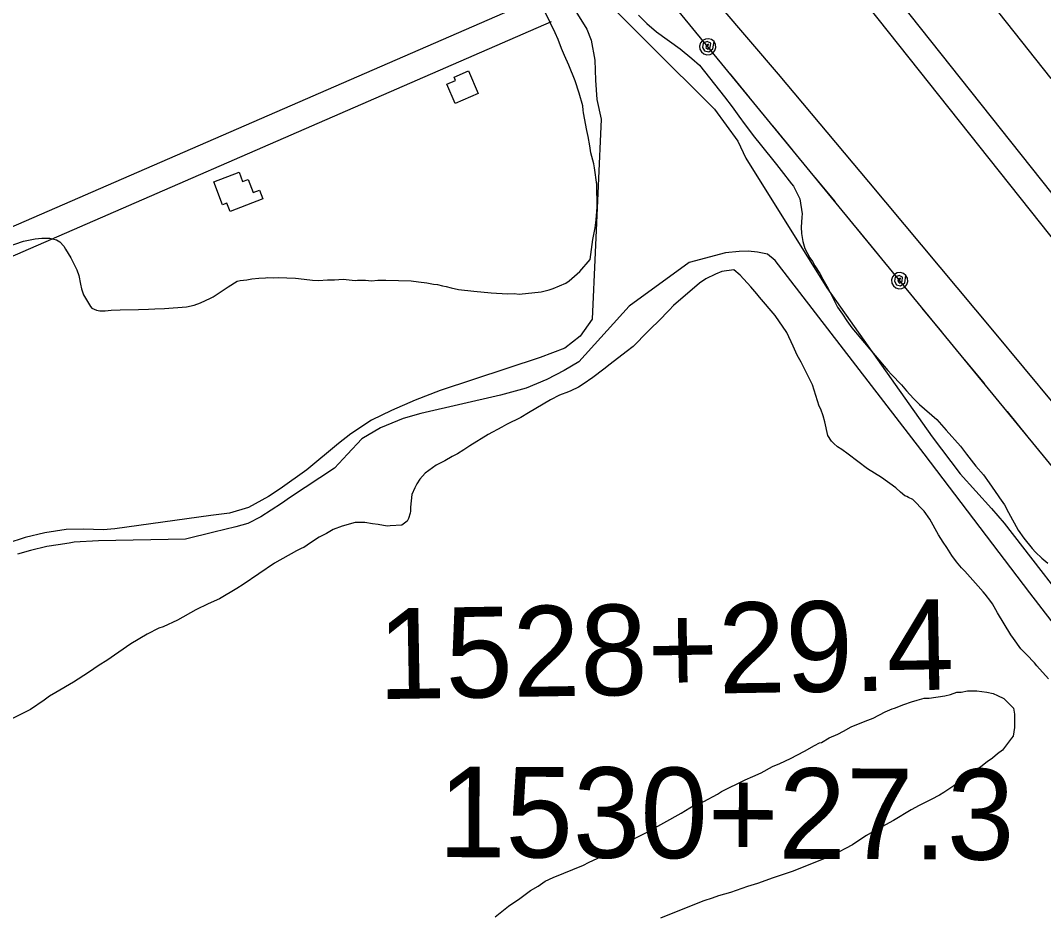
# Model space of a CAD drawing. Extents: x 3187622 to 3225504, y 800805 to 826213.
# Drawn here: x 3203301 to 3204430, y 808726 to 809710 of the extents above; entities that cross this region are included whole.
import ezdxf

# ---------------------------------------------------------------- set-up
doc = ezdxf.new("R2010")
doc.units = 0
for name, color, linetype in [('V-BLDG-OTLN', 7, 'Continuous'), ('V-LEVE-TOET', 7, 'Continuous'), ('V-ROAD-CNTR', 7, 'Continuous'), ('V-SITE-VEGE', 7, 'Continuous'), ('V-SURV-IDEN', 7, 'Continuous'), ('V-SURV-LINE', 7, 'Continuous'), ('V-TOPO-SHOR', 7, 'Continuous'), ('V-UTIL-LINE', 7, 'Continuous')]:
    doc.layers.add(name, color=color, linetype=linetype)

msp = doc.modelspace()

# ---------------------------------------------------------------- linework, layer by layer
at = {"layer": 'V-BLDG-OTLN'}
for points in [[(3203795, 809653.8), (3203805.8, 809628.8), (3203780.3, 809617.8), (3203771.1, 809639), (3203780.7, 809643.2), (3203779.1, 809646.9)], [(3203513.8, 809531.2), (3203541.8, 809542), (3203545.8, 809531.6), (3203551.9, 809533.9), (3203557.4, 809519.5), (3203564.2, 809522.1), (3203567.9, 809512.5), (3203531.9, 809498.7), (3203528.5, 809507.7), (3203523.6, 809505.8)]]:
    msp.add_lwpolyline(points, close=True, dxfattribs=at)
at = {"layer": 'V-LEVE-TOET'}
for points in [[(3204438, 809645.6), (3204331.1, 809780.7), (3204223.6, 809909.6), (3204107.9, 810046.1), (3204012.5, 810171.7), (3203907, 810306.8), (3203783.9, 810457.5), (3203673.5, 810594.7), (3203550, 810751.7)], [(3203299.1, 810717.9), (3203435, 810536.1), (3203555.5, 810372.6), (3203703.7, 810183.8), (3203883.2, 809963.1), (3204040.6, 809762.8), (3204136.7, 809650.3), (3204236.5, 809531.2), (3204373.2, 809367.6), (3204510.1, 809202.5), (3204637.2, 809051.1), (3204773.8, 808887.8), (3204803.8, 808858.4), (3204837.8, 808827), (3204886.8, 808794.6), (3204948.5, 808758.4), (3205022.9, 808715)]]:
    msp.add_lwpolyline(points, dxfattribs=at)
at = {"layer": 'V-ROAD-CNTR'}
for points in [[(3202020.9, 808914.4), (3202071.7, 808944.4), (3202530.7, 809144.7), (3203120.6, 809407.7), (3203874.8, 809736)], [(3202036.2, 808888.6), (3202085.3, 808917.6), (3202542.9, 809117.3), (3203132.6, 809380.2), (3203886.8, 809708.4)]]:
    msp.add_lwpolyline(points, dxfattribs=at)
at = {"layer": 'V-SITE-VEGE'}
for points in [[(3203348.4, 809460.2), (3203350.1, 809457.1), (3203356.2, 809447.4), (3203362.8, 809434.2), (3203364.9, 809428), (3203366.7, 809418.4), (3203367.9, 809413.1), (3203370.1, 809406.5), (3203378, 809393.7), (3203379.3, 809391.9), (3203384.5, 809389.7), (3203388.1, 809388.8), (3203394.2, 809388.8), (3203400.8, 809389.7), (3203410.5, 809390.1), (3203430.7, 809390.4), (3203441.7, 809390.8), (3203448.7, 809391.2), (3203459.7, 809391.6), (3203483.9, 809393.2), (3203492.2, 809395), (3203499.3, 809397.6), (3203510.3, 809402.8), (3203513.4, 809404.5), (3203529.7, 809415.5), (3203539.8, 809421.6), (3203542.9, 809422.4), (3203550.4, 809423.3), (3203556.1, 809424.1), (3203563.6, 809425), (3203571, 809425.4), (3203573.2, 809425.8), (3203579.4, 809425.3), (3203585.1, 809425.7), (3203604, 809424.8), (3203619.8, 809423), (3203622.9, 809422.9), (3203629.5, 809422.5), (3203639.6, 809423.3), (3203647, 809423.3), (3203656.7, 809423.7), (3203669.9, 809422.3), (3203672.5, 809422.7), (3203681.3, 809422.7), (3203687.9, 809422.2), (3203694.9, 809422.6), (3203703.7, 809422.6), (3203731.9, 809422), (3203739.8, 809421.1), (3203749, 809419.7), (3203756.4, 809418.4), (3203760.8, 809417.9), (3203766.5, 809416.6), (3203770.5, 809415.7), (3203775.8, 809414.4), (3203784.1, 809412.6), (3203800.8, 809410.7), (3203820.1, 809408.9), (3203838.1, 809407.5), (3203845.6, 809407.9), (3203850.9, 809407.4), (3203875.1, 809410), (3203883.9, 809412.1), (3203888.3, 809413.4), (3203902.3, 809419.5), (3203906.3, 809422.1), (3203917.8, 809432.2), (3203929.3, 809445.7), (3203932.4, 809467.7), (3203934.7, 809480.4), (3203936.1, 809489.2), (3203937, 809503.3), (3203936.7, 809528.3), (3203934.1, 809546.8), (3203933.3, 809551.2), (3203930.2, 809563.5), (3203928.9, 809571), (3203927.2, 809581.5), (3203925.5, 809588.1), (3203922.1, 809607.5), (3203921.7, 809610.6), (3203921.2, 809615.4), (3203917.3, 809629.1), (3203912.6, 809642.7), (3203905.6, 809660.3), (3203900.8, 809670.9), (3203897.8, 809678.4), (3203893.9, 809688.5), (3203890.8, 809696), (3203879.9, 809718)], [(3203982.8, 809715.3), (3203991.9, 809706.1), (3204002.5, 809696.8), (3204028.7, 809678.2), (3204041.4, 809667.6), (3204049.8, 809660.1), (3204077.7, 809625.3), (3204086, 809614.2), (3204093.4, 809603.7), (3204100.4, 809594.4), (3204110.5, 809580.7), (3204117, 809572.8), (3204135, 809550.3), (3204140.2, 809543.7), (3204151.6, 809529.1), (3204153.7, 809526.5), (3204156.8, 809520.8), (3204160.7, 809512.4), (3204163.3, 809496.1), (3204162.8, 809492.2), (3204162.3, 809481.2), (3204162.7, 809474.2), (3204164, 809465.4), (3204166.2, 809457.9), (3204171.8, 809447.3), (3204174.5, 809443.3), (3204177.1, 809438.5), (3204182.8, 809430.1), (3204186.2, 809423.9), (3204191.9, 809413.4), (3204202.4, 809393.1), (3204207.6, 809385.2), (3204212.4, 809377.7), (3204218.1, 809370.2), (3204257.9, 809323), (3204261.8, 809318.6), (3204272.7, 809307.1), (3204278.4, 809300.5), (3204286.3, 809292.1), (3204292.9, 809285.5), (3204311.7, 809269.1), (3204322.2, 809257.2), (3204337.9, 809239.6), (3204344.5, 809230.8), (3204355, 809217.5), (3204363.3, 809207.8), (3204369.8, 809199), (3204379.4, 809184.5), (3204381.2, 809182.3), (3204386.4, 809174.8), (3204390.8, 809166.4), (3204401.7, 809146.6), (3204407.8, 809137.8), (3204416.9, 809126.3), (3204420.9, 809122.3), (3204427.9, 809115.7), (3204434.5, 809110.4)], [(3203283.8, 809458.7), (3203304, 809465.7), (3203316.8, 809468.3), (3203324.3, 809469.1), (3203333, 809469.1), (3203340.5, 809467.3), (3203344, 809465.1), (3203348.4, 809460.2)], [(3204422.1, 808997.1), (3204419.5, 809000.2), (3204410.7, 809009.4), (3204404.6, 809015.6), (3204396.3, 809027.1), (3204393.7, 809031), (3204378.8, 809055.3), (3204373.2, 809065.4), (3204371.4, 809068.1), (3204365.3, 809076), (3204363.1, 809078.6), (3204357.4, 809084.8), (3204342.6, 809101.6), (3204339.1, 809105.1), (3204333.4, 809111.7), (3204328.6, 809118.8), (3204322.9, 809127.6), (3204319, 809133.3), (3204313.7, 809141.7), (3204304.2, 809158.9), (3204298, 809167.7), (3204285.4, 809180.5), (3204280.5, 809182.7), (3204278.8, 809184), (3204276.6, 809184.5), (3204271.8, 809188.5), (3204266.5, 809193.3), (3204250.7, 809204.8), (3204235.4, 809214.6), (3204213.9, 809230.5), (3204206.9, 809235.8), (3204202.1, 809238.9), (3204198.2, 809242.4), (3204195.6, 809245.1), (3204191.6, 809251.2), (3204188.2, 809266.2), (3204186.5, 809272.8), (3204183.8, 809280.3), (3204182.1, 809283.8), (3204174.7, 809307.1), (3204166, 809324.7), (3204162.1, 809332.2), (3204157.7, 809340.1), (3204153.4, 809349.8), (3204146.4, 809364.8), (3204133.3, 809383.8), (3204116.3, 809404), (3204113.2, 809407.6), (3204106.7, 809415.5), (3204094.9, 809428.3), (3204087.9, 809434.1), (3204074.7, 809432.4), (3204067.6, 809429.3), (3204057, 809424.1), (3204050, 809419.3), (3204021.3, 809394.8), (3204016.5, 809389.6), (3204012.9, 809386.1), (3204008.5, 809381.2), (3203993.1, 809365.9), (3203976.7, 809349.7), (3203969.2, 809343.6), (3203951.2, 809330.1), (3203944.5, 809324.4), (3203932.2, 809315.2), (3203921.6, 809307.8), (3203916.3, 809304.7), (3203908, 809300.4), (3203905.3, 809299.5), (3203895.6, 809295.6), (3203885.5, 809290.8), (3203869.2, 809281.2), (3203861.3, 809276.4), (3203852.9, 809271.2), (3203837.1, 809263.4), (3203831.8, 809260.3), (3203816.8, 809252.5), (3203796.5, 809239.8), (3203789.9, 809235.4), (3203782.9, 809231.1), (3203777.1, 809228), (3203768.8, 809223.2), (3203759.5, 809218.4), (3203747.2, 809209.7), (3203741.4, 809203.1), (3203737.9, 809197.9), (3203735.7, 809193.5), (3203732.6, 809186), (3203731.2, 809172), (3203731.2, 809167.6), (3203730.7, 809165.4), (3203728.9, 809159.7), (3203727.2, 809156.6), (3203721.4, 809152.2), (3203708.7, 809151.4), (3203705.2, 809151), (3203695.5, 809152.8), (3203688.9, 809153.7), (3203680.6, 809155.1), (3203670, 809155.1), (3203655.5, 809151.2)], [(3203655.5, 809151.2), (3203645.8, 809147.3), (3203638.3, 809142.9), (3203630.4, 809139), (3203620.7, 809132.9), (3203613.2, 809127.7), (3203611, 809126.8), (3203605.3, 809123.8), (3203581.1, 809110.2), (3203546.2, 809086.7), (3203539.2, 809082.3), (3203520.2, 809071), (3203507.9, 809065.3), (3203494.2, 809058.8), (3203474, 809047.4), (3203458.1, 809040), (3203453.3, 809038.7), (3203440.5, 809031.8), (3203422.5, 809021.3), (3203396, 809003), (3203387.6, 808997.7), (3203375.7, 808989.4), (3203359, 808979), (3203339.6, 808967.6), (3203332.5, 808963.3), (3203326.8, 808958.9), (3203311.8, 808948.8), (3203291.1, 808938.4)], [(3204435.2, 808982.5), (3204422.1, 808997.1)], [(3203824.5, 808719.9), (3203839.1, 808731.6), (3203851.7, 808739.9), (3203863.5, 808748.8), (3203871.8, 808753.6), (3203879.5, 808759.2), (3203888.5, 808763.3), (3203921.9, 808777), (3203927.4, 808779.8), (3203937.8, 808784.6), (3203948.3, 808790.1), (3203963.6, 808798.3), (3203974.7, 808804.5), (3203991.4, 808812.8), (3204029.6, 808834.1), (3204044.2, 808843), (3204054.6, 808847.1), (3204069.9, 808855.4), (3204074.1, 808858.2), (3204100.5, 808871.2), (3204108.8, 808874.6), (3204117.9, 808878.8), (3204130.4, 808885.6), (3204138.7, 808889.1), (3204150.5, 808894.6), (3204165.8, 808902.8), (3204177, 808909), (3204182.5, 808911.8), (3204184.6, 808912.4), (3204192.9, 808917.3), (3204202.7, 808921.4), (3204208.9, 808924.8), (3204217.3, 808929.6), (3204232.6, 808935.8), (3204241.6, 808939.2), (3204254.8, 808946.1), (3204262.4, 808949.6), (3204265.2, 808950.2), (3204275.6, 808954.3), (3204284, 808957.1), (3204290.2, 808959.1), (3204297.9, 808961.2), (3204303.4, 808961.2), (3204320.8, 808963.9), (3204327, 808965.2), (3204334, 808968), (3204338.8, 808967.9), (3204345.7, 808969.3), (3204356.1, 808969.2), (3204367.2, 808967.8), (3204374.2, 808966.4), (3204379, 808964.3), (3204385.9, 808960.8), (3204396.3, 808950.3), (3204397.6, 808943.4), (3204397.6, 808928.8), (3204396.9, 808924), (3204396.1, 808919.1), (3204394.1, 808917.1), (3204384.3, 808903.9), (3204378.7, 808899.8), (3204373.2, 808895), (3204367.6, 808890.8), (3204360.6, 808885.3), (3204352.3, 808879.8), (3204330.7, 808864.6), (3204319.6, 808857.1), (3204314.7, 808854.3), (3204305.7, 808849.5), (3204292.5, 808842.6), (3204283.4, 808837.8), (3204264, 808826.1), (3204259.1, 808823.4), (3204243.8, 808815.1), (3204234.1, 808809.6), (3204222.3, 808802), (3204218.8, 808799.3), (3204196.5, 808787.6), (3204153.5, 808770.4), (3204131.2, 808762.9), (3204113.9, 808756.7), (3204102.8, 808753.3), (3204084, 808746.5), (3204070.8, 808743.1), (3204063.9, 808740.3), (3204054.8, 808737.6), (3204040.9, 808732.1)], [(3204040.9, 808732.1), (3204006.9, 808718.4)]]:
    msp.add_lwpolyline(points, dxfattribs=at)
at = {"layer": 'V-SURV-LINE'}
for points in [[(3203413.3, 810809.8), (3204794.7, 809070.1)], [(3204771.2, 809051.5), (3203389.8, 810791.1)]]:
    msp.add_lwpolyline(points, dxfattribs=at)
at = {"layer": 'V-TOPO-SHOR'}
for points in [[(3203489, 810266.1), (3203569.7, 810187.9), (3203704.2, 810030.8), (3203829.4, 809874), (3203922, 809755.8), (3204066.6, 809611.5), (3204092.1, 809576.2), (3204101.1, 809557.3), (3204190.6, 809414.4), (3204306.9, 809249.9), (3204337.7, 809209.1), (3204372.3, 809170.7), (3204386, 809154.5), (3204478.6, 809035.3), (3204493.4, 809014.9), (3204516.7, 808982.8), (3204542.8, 808954.9), (3204549.7, 808944.6), (3204627.6, 808858.4), (3204647.3, 808835.8), (3204666.5, 808813.2), (3204681.3, 808799.2), (3204700.3, 808780.7), (3204765.6, 808730.7)], [(3203876.1, 809780.2), (3203925.7, 809699.9), (3203930.4, 809687.7), (3203934.6, 809665.5), (3203935.1, 809643.6), (3203936.6, 809622.3), (3203941.5, 809600.4), (3203931.4, 809379.8), (3203918.1, 809360.9), (3203901.3, 809347.6), (3203874.2, 809337.3), (3203763.9, 809300.8), (3203736.1, 809290.1), (3203710, 809279), (3203688, 809268), (3203665.1, 809253.1), (3203651.6, 809242.3), (3203616.7, 809213.5), (3203587.1, 809192.3), (3203574.2, 809183.9), (3203552.4, 809171.7), (3203531.1, 809165.5), (3203510.8, 809163), (3203404.9, 809148.3), (3203391.7, 809147.2), (3203370.4, 809147.9), (3203351.1, 809147.6), (3203327.6, 809143.7), (3203305.6, 809138.5), (3203285.7, 809132.1)], [(3204555.8, 808894.4), (3204414.5, 809077.4), (3204297.8, 809231), (3204177.9, 809386.6), (3204133.6, 809444.4), (3204124.9, 809451.4), (3204114.1, 809453.6), (3204103.8, 809454.6), (3204093.7, 809454.3), (3204078.5, 809452.8), (3204038.6, 809442.1), (3203972.3, 809393.9), (3203916.8, 809332.5), (3203900.6, 809323.1), (3203881.6, 809313.1), (3203858.5, 809303.4), (3203830.2, 809295.8), (3203742.5, 809275.7), (3203723, 809270), (3203697.8, 809259.7), (3203677.3, 809247.5), (3203661.4, 809230.6), (3203647.1, 809215.1), (3203598.7, 809183), (3203588.6, 809176.3), (3203566, 809161.6), (3203551.4, 809154.2), (3203538.1, 809150.3), (3203513.8, 809144.7), (3203482.8, 809136.9), (3203386.7, 809134.8), (3203359.9, 809133.5), (3203354.3, 809132.5), (3203342.1, 809130.6), (3203329.5, 809128.7), (3203311.7, 809124.2), (3203297.3, 809120.4)]]:
    msp.add_lwpolyline(points, dxfattribs=at)
at = {"layer": 'V-UTIL-LINE'}
for points in [[(3199923.1, 813594.5), (3200640, 812717.8), (3202006.1, 811098.7), (3203128.7, 810686.1), (3203334.1, 810414.1), (3203687.1, 810134), (3205008, 808523.1), (3206197, 808326.5), (3208534.5, 807926.9), (3209217.7, 808075.2), (3210991.3, 807487.7), (3211714.8, 807276.3), (3211555.1, 806654.5), (3211454.6, 806207.4)], [(3204059, 809680.4), (3204059.8, 809683.2), (3204057.6, 809682.4), (3204056.9, 809679.8), (3204059, 809677.7), (3204061.8, 809679.8), (3204062.3, 809684.4), (3204058.5, 809686.3), (3204054.1, 809684.3), (3204053.4, 809679.8), (3204055.4, 809675.8), (3204060.1, 809674.9), (3204064.6, 809678.1), (3204066, 809686.1), (3204063.3, 809688.4), (3204059.9, 809689.4), (3204056.4, 809689), (3204053.3, 809687.4), (3204051.1, 809684.7), (3204050.1, 809681.3), (3204050.4, 809677.8), (3204052.1, 809674.7), (3204054.8, 809672.5), (3204058.2, 809671.5), (3204061.6, 809671.8), (3204064.7, 809673.5), (3204067, 809676.2), (3204068, 809679.5), (3204067.7, 809683), (3204066, 809686.1)], [(3204083.8, 809650.3), (3204105.3, 809624)], [(3204130.7, 809593.1), (3204152.2, 809566.8)], [(3204177.6, 809535.8), (3204199.2, 809509.5)], [(3204224.5, 809478.6), (3204246.1, 809452.3)], [(3204270.8, 809422.2), (3204271.6, 809424.9), (3204269.4, 809424.2), (3204268.7, 809421.5), (3204270.8, 809419.5), (3204273.5, 809421.5), (3204274.1, 809426.1), (3204270.3, 809428), (3204265.8, 809426), (3204265.2, 809421.5), (3204267.2, 809417.5), (3204271.9, 809416.6), (3204276.4, 809419.8), (3204277.8, 809427.9), (3204275.1, 809430.1), (3204271.7, 809431.1), (3204268.2, 809430.8), (3204265.1, 809429.1), (3204262.9, 809426.4), (3204261.9, 809423), (3204262.2, 809419.5), (3204263.9, 809416.5), (3204266.6, 809414.2), (3204269.9, 809413.2), (3204273.4, 809413.5), (3204276.5, 809415.2), (3204278.8, 809417.9), (3204279.8, 809421.3), (3204279.4, 809424.8), (3204277.8, 809427.9)], [(3204295.5, 809392), (3204317.1, 809365.7)], [(3204342.5, 809334.8), (3204364, 809308.5)], [(3204389.4, 809277.6), (3204410.9, 809251.3)]]:
    msp.add_lwpolyline(points, dxfattribs=at)

# ---------------------------------------------------------------- texts
at = {"layer": 'V-SURV-IDEN'}
for s, rotation, p in [('1528+29.4', 0.9647, (3203695.8, 808960.1)), ('1530+27.3', 359.7263, (3203761.4, 808785.8))]:
    msp.add_text(s, height=100, rotation=rotation, dxfattribs=at).set_placement(p)

doc.saveas('drawing.dxf')
